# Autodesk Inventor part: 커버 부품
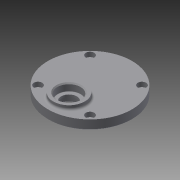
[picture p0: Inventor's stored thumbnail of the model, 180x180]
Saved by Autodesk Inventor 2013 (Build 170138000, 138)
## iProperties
Created: 2015-07
Part Number: 커버 부품
Material: 일반
Document SubType Name: Modeling
Designer: user
Density: 1 g/cm^3
Author: user
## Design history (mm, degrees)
sketch "스케치1"
  geometry: C1 r 40 at (0, 0); 1 further point
  constraints: 1 centre point, 1 coincident
  dimensions: "d0" = 80 diameter of C1
extrude "돌출1" new body sketch "스케치1" distance "d1" = 9; taper "d2" = 0 deg
sketch "스케치2"
  geometry: L1 (0, 0)-(0, 11); L2 (0, 0)-(0, -20); C1 r 40 at (0, 0) reference; C2 r 14 at (0, 11); C3 r 14 at (0, -20)
  constraints: 4 end point, 2 centre point, 2 coincident, 1 collinear, 1 vertical
  dimensions: "d3" = 11 distance of L1.start L1.end; "d4" = 20 distance of L1.start L2.end; "d5" = 28 diameter of C2; "d6" = 28 diameter of C3
extrude "돌출2" join sketch "스케치2" distance "d7" = 3; taper "d8" = 0 deg
sketch "스케치3"
  geometry: L1 (0, 0)-(0, -20); C1 r 40 at (0, 0) reference; C2 r 15 at (0, -20)
  constraints: 2 end point, 1 centre point, 1 coincident, 1 vertical
  dimensions: "d9" = 20 distance of L1.start L1.end; "d11" = 30 diameter of C2
extrude "돌출3" join sketch "스케치3" distance "d12" = 4; taper "d13" = 0 deg
fillet "모깎기1" dims "d14" = 2
chamfer "모따기1" distance "d15" = 1; stored, may be unused: second distance "d16" = 2, angle "d17" = 45 deg
hole "구멍1" diameter "d20" = 15; stored, may be unused: countersink angle "d24" = 90 deg, drill point angle "d26" = 0 deg; dims "d18" = 10, "d19" = 10, "d21" = 6, "d22" = 22, "d23" = 7, "d25" = 10
hole "구멍2" diameter "d29" = 22; stored, may be unused: countersink angle "d33" = 90 deg, drill point angle "d35" = 0 deg; dims "d27" = 10, "d28" = 10, "d30" = 6, "d31" = 22, "d32" = 7, "d34" = 7
hole "구멍3" diameter "d38" = 18; stored, may be unused: countersink angle "d42" = 90 deg, drill point angle "d44" = 0 deg; dims "d36" = 10, "d37" = 10, "d39" = 6, "d40" = 22, "d41" = 7, "d43" = 8
chamfer "모따기2" distance "d45" = 1; stored, may be unused: second distance "d46" = 2, angle "d47" = 45 deg
fillet "모깎기2" dims "d48" = 0.3
fillet "모깎기3" dims "d49" = 2
sketch "스케치4" dims "d50" = 70
  geometry: L1 (0, 0)-(24.749, 24.749); L2 (0, 0)-(35, 0); C1 r 40 at (0, 0) reference
  constraints: 4 end point, 1 coincident, 1 equal length, 1 horizontal, 3 other
  dimensions: "d51" = 45 deg angle of L2 L1
hole "구멍4" sketch "스케치4" at (24.749, 24.749) diameter "d52" = 4.5; stored, may be unused: countersink angle "d56" = 90 deg, drill point angle "d58" = 0 deg; dims "d53" = 6, "d54" = 8, "d55" = 4.4, "d57" = 10
node "솔리드1"
pattern_circular "원형 패턴1" dims angle "d60" = 360 deg
